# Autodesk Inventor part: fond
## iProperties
Created: 2011-01
Part Number: fond
Document SubType Name: Modeling
Designer: eric
Density: 1 g/cm^3
Mass: 19.5001 g
Surface Area: 269.199 cm^2
Volume: 19.5001 cm^3
Author: eric
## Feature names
1. Base1
